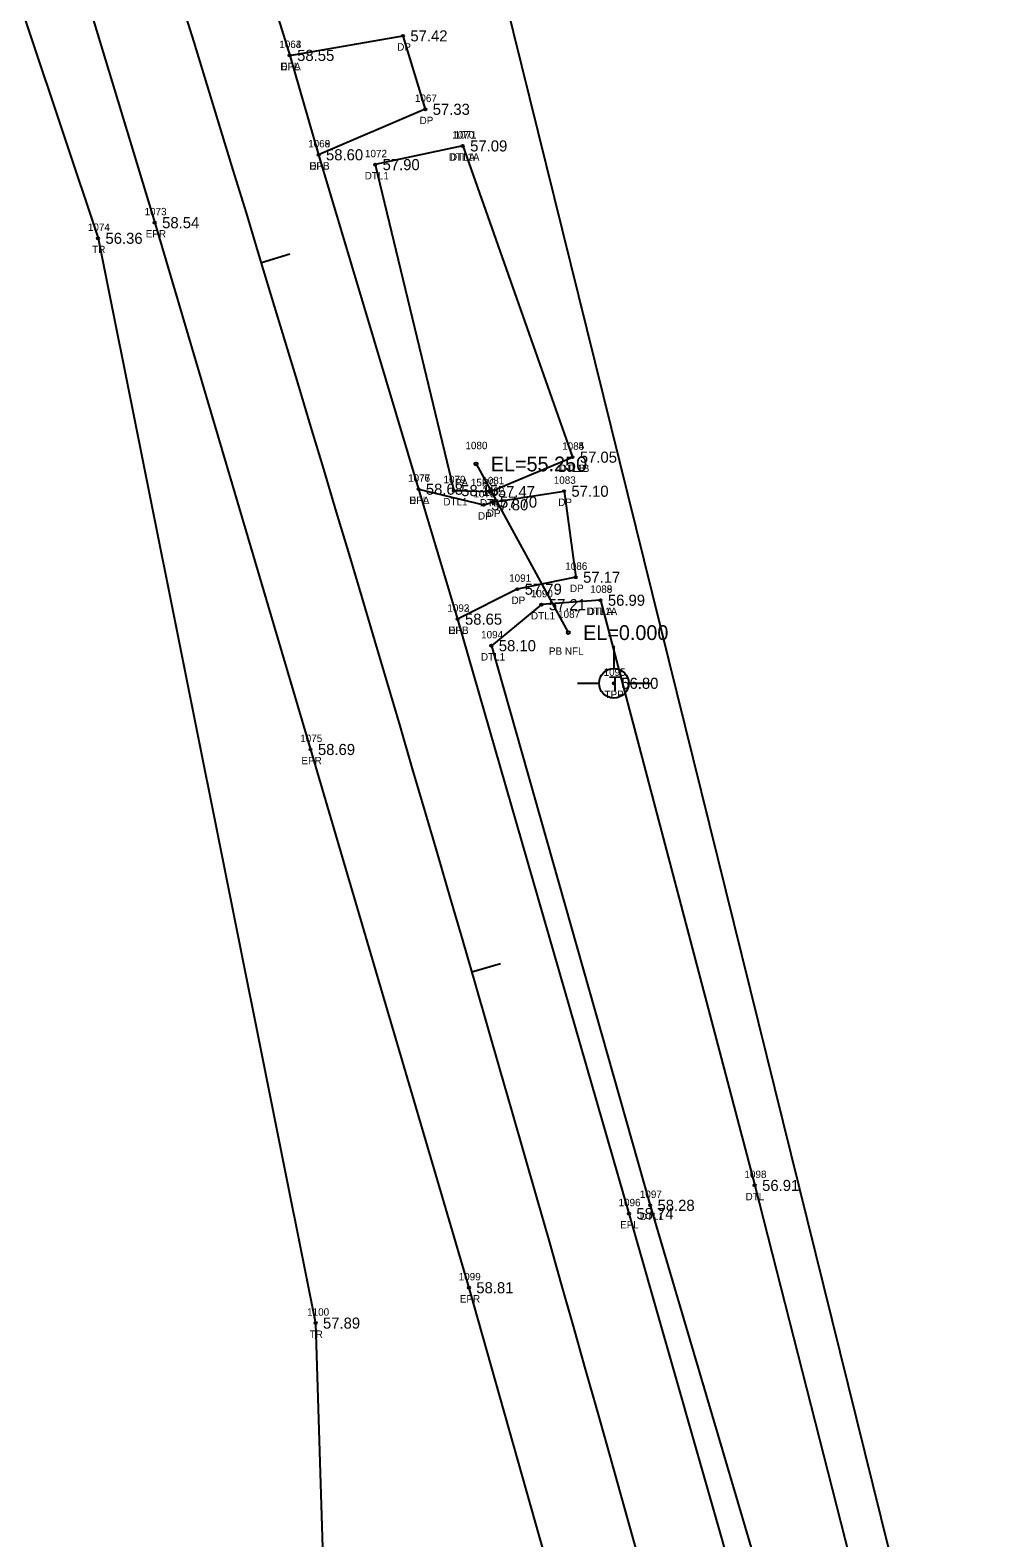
# Model space of a CAD drawing. Extents: x 2396531 to 2397633, y 770203 to 772837.
# Drawn here: x 2396869.2 to 2396999.7, y 771777.9 to 771981.7 of the extents above; entities that cross this region are included whole.
import ezdxf

# ---------------------------------------------------------------- set-up
doc = ezdxf.new("R2010")
doc.units = 0
for name, color, linetype in [('RD_EX_DR_Pipe', 7, 'Continuous'), ('RD_EX_DR_Pipe_txCode', 7, 'Continuous'), ('RD_EX_Driveway', 7, 'Continuous'), ('RD_EX_Driveway_txCode', 7, 'Continuous'), ('RD_EX_H2O', 7, 'Continuous'), ('RD_EX_H2O_txCode', 7, 'Continuous'), ('RD_EX_Road', 7, 'Continuous'), ('RD_EX_Road_txCode', 7, 'Continuous'), ('RD_EX_TX_Driveway_ELEV', 7, 'Continuous'), ('RD_EX_TX_H2O_ELEV', 7, 'Continuous'), ('RD_EX_TX_Road_ELEV', 7, 'Continuous'), ('RD_EX_TX_UT_ELEV', 7, 'Continuous'), ('RD_EX_TX_VEG_ELEV', 7, 'Continuous'), ('RD_EX_UT', 7, 'Continuous'), ('RD_EX_UT_txCode', 7, 'Continuous'), ('RD_EX_VEG', 7, 'Continuous'), ('RD_EX_VEG_txCode', 7, 'Continuous'), ('RD_HC_Cl', 7, 'Continuous'), ('RD_HC_Data_Tic', 7, 'Continuous'), ('RD_SMD_Locator', 7, 'Continuous'), ('RD_TX_Pipe_ElevEX', 7, 'Continuous')]:
    doc.layers.add(name, color=color, linetype=linetype)

msp = doc.modelspace()

# ---------------------------------------------------------------- linework, layer by layer
at = {"layer": 'RD_EX_DR_Pipe'}
msp.add_line((2396929.52, 771923.09), (2396942, 771900.29), dxfattribs=at)
at = {"layer": 'RD_EX_Driveway'}
for points in [[(2396904.34, 771978.33), (2396919.65, 771980.97), (2396922.67, 771971.04), (2396908.24, 771964.89)], [(2396921.74, 771919.68), (2396930.57, 771917.57), (2396931.76, 771917.94), (2396941.42, 771919.41), (2396943, 771907.78), (2396935.1, 771906.16), (2396927.03, 771902.11)]]:
    msp.add_lwpolyline(points, dxfattribs=at)
at = {"layer": 'RD_EX_H2O'}
msp.add_line((2396927.73, 771966.09), (2396942.56, 771924.01), dxfattribs=at)
for points in [[(2396927.73, 771966.09), (2396915.89, 771963.56), (2396926.52, 771919.49), (2396931.47, 771919.35), (2396942.56, 771924.01)], [(2396946.35, 771904.67), (2396938.36, 771904.07), (2396931.6, 771898.52), (2396953.06, 771822.86), (2396974.04, 771751.81), (2396987.33, 771718.09)], [(2396946.35, 771904.67), (2396967.2, 771825.55), (2396985.22, 771754.85), (2396997.16, 771723.28), (2396993.62, 771717.84), (2396987.33, 771718.09)]]:
    msp.add_lwpolyline(points, dxfattribs=at)
at = {"layer": 'RD_EX_Road'}
for points in [[(2396680.92, 772617.84), (2396715.6, 772525.73), (2396750.68, 772430.62), (2396786.3, 772332.21), (2396811.38, 772263.31), (2396839.69, 772181.74), (2396863.75, 772109.83), (2396883.63, 772046.56), (2396889.54, 772027.11), (2396896.25, 772004.37), (2396904.34, 771978.33), (2396908.24, 771964.89), (2396921.74, 771919.68), (2396927.03, 771902.11), (2396950.2, 771821.74), (2396970.47, 771750.68), (2396978.33, 771721.29), (2396990.58, 771675.04), (2397004.94, 771620.49), (2397034.26, 771508.8), (2397061.11, 771410.49), (2397060.64, 771407.04), (2397062.07, 771407.67)], [(2396658.78, 772611.07), (2396693.37, 772516.9), (2396729.65, 772418.78), (2396760.7, 772333.11), (2396788.58, 772254.87), (2396814.65, 772181.57), (2396841.1, 772100.86), (2396861.19, 772037.76), (2396886.09, 771955.71), (2396907.15, 771884.49), (2396928.56, 771811.72), (2396947.65, 771744.09), (2396985.17, 771602.64), (2397011.11, 771504.04), (2397037.95, 771404.25), (2397039, 771401.22)]]:
    msp.add_lwpolyline(points, dxfattribs=at)
at = {"layer": 'RD_EX_UT'}
for p, q in [((2396948.16, 771898.51), (2396948.16, 771895.44)), ((2396943.23, 771893.45), (2396946.16, 771893.45)), ((2396950.16, 771893.45), (2396953.23, 771893.45))]:
    msp.add_line(p, q, dxfattribs=at)
msp.add_circle((2396948.16, 771893.44), 2, dxfattribs=at)
at = {"layer": 'RD_EX_VEG'}
for points in [[(2396666.35, 772324.52), (2396746.5, 772348.13), (2396878.43, 771953.6), (2396907.83, 771806.94), (2396910.04, 771736.08), (2396945.43, 771592.11), (2397049.51, 771229.15), (2396980.16, 771221.67)], [(2396927.91, 772008.32), (2396999.71, 771718.21), (2397059.32, 771736.23), (2397119.67, 771755.84)]]:
    msp.add_lwpolyline(points, dxfattribs=at)
at = {"layer": 'RD_HC_Cl'}
msp.add_arc((2389304.02, 769643.48), 7939.03, 14.59125, 20.164785, dxfattribs=at)
at = {"layer": 'RD_HC_Data_Tic'}
for p, q in [((2396900.52, 771950.31), (2396904.35, 771951.48)), ((2396928.97, 771854.45), (2396932.81, 771855.56))]:
    msp.add_line(p, q, dxfattribs=at)
at = {"layer": 'RD_SMD_Locator'}
for centre, radius in [((2396919.65, 771980.97), 0.15), ((2396904.34, 771978.33), 0.15), ((2396904.34, 771978.33), 0.15), ((2396922.67, 771971.04), 0.15), ((2396908.24, 771964.89), 0.15), ((2396908.24, 771964.89), 0.15), ((2396927.73, 771966.09), 0.15), ((2396927.73, 771966.09), 0.15), ((2396915.89, 771963.56), 0.15), ((2396886.09, 771955.71), 0.15), ((2396878.43, 771953.6), 0.15), ((2396942.56, 771924.01), 0.15), ((2396942.56, 771924.01), 0.15), ((2396929.52, 771923.09), 0.2), ((2396921.74, 771919.68), 0.15), ((2396921.74, 771919.68), 0.15), ((2396926.52, 771919.49), 0.15), ((2396931.47, 771919.35), 0.15), ((2396941.42, 771919.41), 0.15), ((2396930.57, 771917.57), 0.15), ((2396931.76, 771917.94), 0.15), ((2396943, 771907.78), 0.15), ((2396935.1, 771906.16), 0.15), ((2396938.36, 771904.07), 0.15), ((2396946.35, 771904.67), 0.15), ((2396946.35, 771904.67), 0.15), ((2396927.03, 771902.11), 0.15), ((2396927.03, 771902.11), 0.15), ((2396942, 771900.29), 0.2), ((2396931.6, 771898.52), 0.15), ((2396948.16, 771893.44), 0.15), ((2396907.15, 771884.49), 0.15), ((2396967.2, 771825.55), 0.15), ((2396950.2, 771821.74), 0.15), ((2396953.06, 771822.86), 0.15), ((2396928.56, 771811.72), 0.15), ((2396907.83, 771806.94), 0.15)]:
    msp.add_circle(centre, radius, dxfattribs=at)

# ---------------------------------------------------------------- texts
at = {"layer": 'RD_EX_DR_Pipe_txCode'}
for s, p in [('1080', (2396928.09, 771925.09)), ('PA 15RC', (2396926.67, 771920.09)), ('1087', (2396940.61, 771902.29)), ('PB NFL', (2396939.38, 771897.29))]:
    msp.add_text(s, height=1, dxfattribs=at).set_placement(p)
at = {"layer": 'RD_EX_Driveway_txCode'}
for s, p in [('1064', (2396902.93, 771979.33)), ('DP', (2396918.87, 771978.97)), ('DPA', (2396903.07, 771976.33)), ('1067', (2396921.26, 771972.04)), ('DP', (2396921.89, 771969.04)), ('1068', (2396906.83, 771965.89)), ('DPB', (2396906.99, 771962.89)), ('1077', (2396920.35, 771920.68)), ('1078', (2396929.18, 771918.57)), ('1082', (2396930.38, 771918.94)), ('1083', (2396940.03, 771920.41)), ('DPA', (2396920.47, 771917.68)), ('DP', (2396940.64, 771917.41)), ('DP', (2396929.79, 771915.57)), ('DP', (2396930.98, 771915.94)), ('1086', (2396941.59, 771908.78)), ('1091', (2396934, 771907.16)), ('DP', (2396942.22, 771905.78)), ('1092', (2396925.65, 771903.11)), ('DP', (2396934.32, 771904.16)), ('DPB', (2396925.78, 771900.11))]:
    msp.add_text(s, height=1, dxfattribs=at).set_placement(p)
at = {"layer": 'RD_EX_H2O_txCode'}
for s, p in [('1070', (2396926.31, 771967.09)), ('1071', (2396926.63, 771967.09)), ('1072', (2396914.51, 771964.56)), ('DTL1A', (2396925.83, 771964.09)), ('DTLA', (2396926, 771964.09)), ('DTL1', (2396914.48, 771961.56)), ('1084', (2396941.17, 771925.01)), ('1085', (2396941.17, 771925.01)), ('1079', (2396925.13, 771920.49)), ('DTL1B', (2396940.68, 771922.01)), ('DTLB', (2396940.84, 771922.01)), ('1081', (2396930.37, 771920.35)), ('DTL1', (2396925.11, 771917.49)), ('DTL1', (2396930.06, 771917.35)), ('1090', (2396936.93, 771905.07)), ('1088', (2396944.97, 771905.67)), ('1089', (2396944.97, 771905.67)), ('DTL1A', (2396944.45, 771902.67)), ('DTLA', (2396944.62, 771902.67)), ('DTL1', (2396936.95, 771902.07)), ('1094', (2396930.21, 771899.52)), ('DTL1', (2396930.19, 771896.52)), ('1098', (2396965.81, 771826.55)), ('1097', (2396951.67, 771823.86)), ('DTL', (2396965.96, 771823.55)), ('DTL1', (2396951.65, 771820.86))]:
    msp.add_text(s, height=1, dxfattribs=at).set_placement(p)
at = {"layer": 'RD_EX_Road_txCode'}
for s, p in [('1063', (2396902.93, 771979.33)), ('EPL', (2396903.13, 771976.33)), ('1069', (2396906.83, 771965.89)), ('EPL', (2396907.04, 771962.89)), ('1073', (2396884.71, 771956.71)), ('EPR', (2396884.87, 771953.71)), ('1076', (2396920.33, 771920.68)), ('EPL', (2396920.53, 771917.68)), ('1093', (2396925.65, 771903.11)), ('EPL', (2396925.83, 771900.11)), ('1075', (2396905.76, 771885.49)), ('EPR', (2396905.92, 771882.49)), ('1096', (2396948.79, 771822.74)), ('EPL', (2396949, 771819.74)), ('1099', (2396927.18, 771812.72)), ('EPR', (2396927.33, 771809.72))]:
    msp.add_text(s, height=1, dxfattribs=at).set_placement(p)
at = {"layer": 'RD_EX_TX_Driveway_ELEV'}
for s, p in [('57.42', (2396920.65, 771980.22)), ('58.55', (2396905.34, 771977.58)), ('57.33', (2396923.67, 771970.29)), ('58.60', (2396909.24, 771964.14)), ('58.68', (2396922.74, 771918.93)), ('57.10', (2396942.42, 771918.66)), ('57.80', (2396931.57, 771916.82)), ('57.70', (2396932.76, 771917.19)), ('57.17', (2396944, 771907.03)), ('57.79', (2396936.1, 771905.41)), ('58.65', (2396928.03, 771901.36))]:
    msp.add_text(s, height=1.5, dxfattribs=at).set_placement(p)
at = {"layer": 'RD_EX_TX_H2O_ELEV'}
for s, p in [('57.09', (2396928.73, 771965.34)), ('57.09', (2396928.73, 771965.34)), ('57.90', (2396916.89, 771962.81)), ('57.05', (2396943.56, 771923.26)), ('57.05', (2396943.56, 771923.26)), ('58.15', (2396927.52, 771918.74)), ('57.47', (2396932.47, 771918.6)), ('56.99', (2396947.35, 771903.92)), ('56.99', (2396947.35, 771903.92)), ('57.21', (2396939.36, 771903.32)), ('58.10', (2396932.6, 771897.77)), ('56.91', (2396968.2, 771824.8)), ('58.28', (2396954.06, 771822.11))]:
    msp.add_text(s, height=1.5, dxfattribs=at).set_placement(p)
at = {"layer": 'RD_EX_TX_Road_ELEV'}
for s, p in [('58.55', (2396905.34, 771977.58)), ('58.60', (2396909.24, 771964.14)), ('58.54', (2396887.09, 771954.96)), ('58.68', (2396922.74, 771918.93)), ('58.65', (2396928.03, 771901.36)), ('58.69', (2396908.15, 771883.74)), ('58.74', (2396951.2, 771820.99)), ('58.81', (2396929.56, 771810.97))]:
    msp.add_text(s, height=1.5, dxfattribs=at).set_placement(p)
at = {"layer": 'RD_EX_TX_UT_ELEV'}
msp.add_text('56.80', height=1.5, dxfattribs=at).set_placement((2396949.16, 771892.69))
at = {"layer": 'RD_EX_TX_VEG_ELEV'}
for s, p in [('56.36', (2396879.43, 771952.85)), ('57.89', (2396908.83, 771806.19))]:
    msp.add_text(s, height=1.5, dxfattribs=at).set_placement(p)
at = {"layer": 'RD_EX_UT'}
msp.add_text('T', height=2, dxfattribs=at).set_placement((2396947.49, 771892.39))
at = {"layer": 'RD_EX_UT_txCode'}
for s, p in [('1095', (2396946.77, 771894.44)), ('TPP', (2396946.89, 771891.44))]:
    msp.add_text(s, height=1, dxfattribs=at).set_placement(p)
at = {"layer": 'RD_EX_VEG_txCode'}
for s, p in [('1074', (2396877.05, 771954.6)), ('TR', (2396877.64, 771951.6)), ('1100', (2396906.69, 771807.94)), ('TR', (2396907.03, 771804.94))]:
    msp.add_text(s, height=1, dxfattribs=at).set_placement(p)
at = {"layer": 'RD_TX_Pipe_ElevEX'}
for s, p in [('EL=55.250', (2396931.52, 771922.09)), ('EL=0.000', (2396944, 771899.29))]:
    msp.add_text(s, height=2, dxfattribs=at).set_placement(p)

doc.saveas('drawing.dxf')
